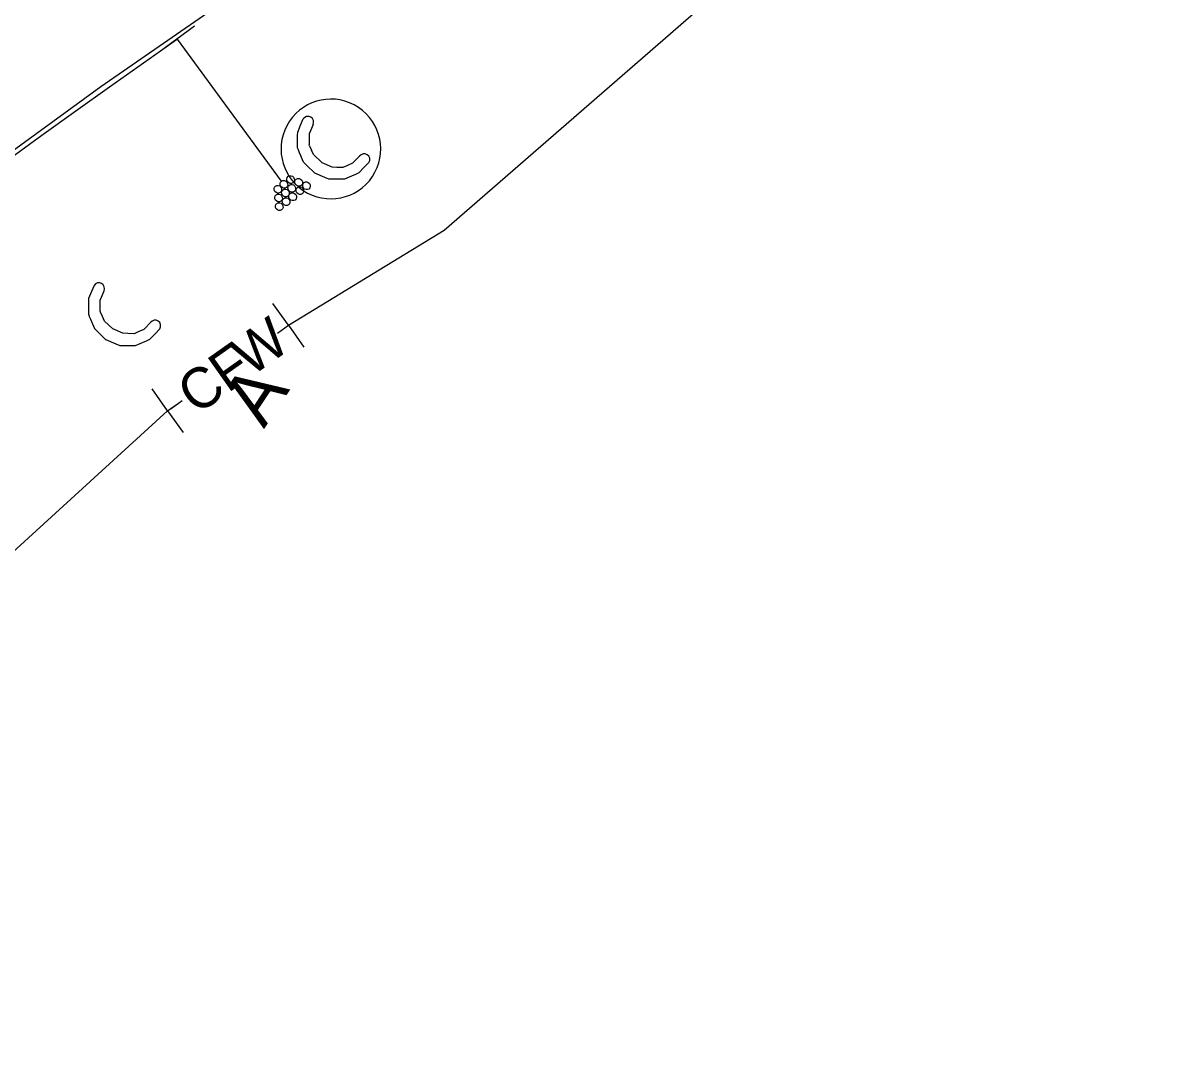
# Model space of a CAD drawing. Extents: x 2357856 to 2382083, y 331121 to 347536.
# Drawn here: x 2380922.9 to 2381137.7, y 332679.3 to 332872.8 of the extents above; entities that cross this region are included whole.
import ezdxf

# ---------------------------------------------------------------- set-up
doc = ezdxf.new("R2010")
doc.units = 0
for name, color, linetype in [('Coir Fiber Wattle Both CELL', 7, 'Continuous'), ('Matting and PSRM Summary Sheet CELL', 7, 'Continuous'), ('Old_Level_12', 7, 'Continuous'), ('P_NCDOT_Horizontal_Alignment_Station_Label', 7, 'Continuous'), ('P_NCDOT_Horizontal_Alignment_Tick_Small', 7, 'Continuous'), ('Sheet Data Field CELL', 7, 'Continuous'), ('Sheet_Named_Boundary', 7, 'Continuous')]:
    doc.layers.add(name, color=color, linetype=linetype)

msp = doc.modelspace()

# ---------------------------------------------------------------- linework, layer by layer
at = {"layer": 'Coir Fiber Wattle Both CELL'}
for radius, start, end in [(2079.999999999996, 122.68319408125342, 138.66862886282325), (2049.9999999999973, 124.90194270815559, 138.73574145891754)]:
    msp.add_arc((2382124.6181357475, 331188.5416706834), radius, start, end, dxfattribs=at)
at = {"layer": 'Matting and PSRM Summary Sheet CELL'}
for p, q in [((2380972.3583073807, 332816.4910176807), (2380969.47078194, 332820.5727081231)), ((2380970.316566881, 332815.0466216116), (2380972.3583073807, 332816.4910176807)), ((2380972.3583073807, 332816.4910176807), (2380975.245832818, 332812.4093272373)), ((2380949.840116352, 332800.5608901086), (2380946.952590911, 332804.6425805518)), ((2380949.840116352, 332800.5608901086), (2380951.881856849, 332802.0052861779)), ((2380950.49325491, 332800.99864639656), (2380952.535077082, 332802.44310024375)), ((2380949.840116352, 332800.5608901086), (2380952.727641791, 332796.47919966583))]:
    msp.add_line(p, q, dxfattribs=at)
at = {"layer": 'Old_Level_12'}
for p, q in [((2380948.234484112, 332867.4813884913), (2380954.8214911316, 332872.29770851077)), ((2380971.0851846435, 332843.3724340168), (2380951.6620882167, 332869.8132461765))]:
    msp.add_line(p, q, dxfattribs=at)
for centre in [(2380972.7568374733, 332843.6688509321), (2380970.387381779, 332841.8505370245), (2380971.52811148, 332842.76817887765), (2380971.7929625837, 332841.16992930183), (2380972.972539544, 332842.03457447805), (2380974.2710181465, 332843.1493205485), (2380974.497022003, 332841.6040676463), (2380975.7257479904, 332842.5047396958), (2380970.515087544, 332840.2332303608), (2380971.9206683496, 332839.5526226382), (2380973.1493943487, 332840.45329468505), (2380970.6427933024, 332838.6159236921)]:
    msp.add_ellipse(centre, major_axis=(-0.44292683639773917, 0.6042551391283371), ratio=0.9273984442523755, dxfattribs=at)
at = {"layer": 'P_NCDOT_Horizontal_Alignment_Station_Label'}
for p, q in [((2380976.4708975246, 332852.7741843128), (2380976.220539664, 332852.1927864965)), ((2380976.96671473, 332853.9132584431), (2380976.4708975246, 332852.7741843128)), ((2380976.217543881, 332851.3103058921), (2380976.2147963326, 332850.14921461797)), ((2380976.220539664, 332852.1927864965), (2380976.217543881, 332851.3103058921)), ((2380976.29185068, 332849.9778304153), (2380976.2147963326, 332850.14921461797)), ((2380976.29185068, 332849.9778304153), (2380976.65943075, 332849.1681692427)), ((2380977.054796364, 332848.3018021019), (2380976.65943075, 332849.1681692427)), ((2380977.054796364, 332848.3018021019), (2380978.576475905, 332846.84706928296)), ((2380978.584044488, 332846.8420332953), (2380978.576475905, 332846.84706928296)), ((2380978.584044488, 332846.8420332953), (2380980.4417666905, 332846.0154198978)), ((2380982.559772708, 332845.94923011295), (2380983.3133683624, 332846.2776790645)), ((2380983.3133683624, 332846.2776790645), (2380984.3983941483, 332846.75140182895)), ((2380984.584806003, 332846.9413006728), (2380984.3983941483, 332846.75140182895)), ((2380984.584806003, 332846.9413006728), (2380985.6267098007, 332848.0046782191)), ((2380980.4417666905, 332846.0154198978), (2380981.403695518, 332845.9841295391)), ((2380981.403695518, 332845.9841295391), (2380982.559772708, 332845.94923011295)), ((2380937.305813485, 332818.95781458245), (2380937.2287591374, 332819.12919878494)), ((2380938.0687591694, 332817.2817862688), (2380937.673393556, 332818.1481534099)), ((2380939.5980072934, 332815.8220174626), (2380939.5904387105, 332815.8270534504)), ((2380945.598768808, 332815.9212848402), (2380945.412356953, 332815.73138599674))]:
    msp.add_line(p, q, dxfattribs=at)
for points in [[(2380987.355627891, 332846.8542898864), (2380986.4968841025, 332845.95021660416), (2380985.4955799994, 332844.8966543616), (2380984.8843897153, 332844.6263236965), (2380984.1433986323, 332844.3004073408), (2380982.8302826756, 332843.72184468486), (2380982.7975049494, 332843.72181548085), (2380982.4445112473, 332843.72465268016), (2380982.383999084, 332843.72396842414), (2380981.618758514, 332843.7308507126), (2380981.086746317, 332843.73541943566), (2380979.9143021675, 332843.7457209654), (2380979.1462588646, 332844.0684017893), (2380977.267133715, 332844.8628487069), (2380977.2595651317, 332844.86788469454), (2380975.752993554, 332846.345323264), (2380975.1650014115, 332846.9221920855), (2380974.813788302, 332847.7564511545), (2380974.7392519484, 332847.93161964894), (2380974.441099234, 332848.6404880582), (2380974.214957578, 332849.1785981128), (2380974.163156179, 332849.3058809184), (2380974.048193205, 332849.5761949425), (2380974.0469269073, 332849.5824972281), (2380974.0647605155, 332850.7908775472), (2380974.080192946, 332851.86436267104), (2380974.090961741, 332852.5123632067), (2380974.6318996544, 332853.8094573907), (2380975.1086798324, 332854.95269111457)], [(2380936.1226426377, 332823.93267528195), (2380935.64586246, 332822.7894415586), (2380935.1049245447, 332821.4923473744), (2380935.0941557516, 332820.84434683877), (2380935.0787233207, 332819.77086171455), (2380935.0608897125, 332818.5624813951), (2380935.0621560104, 332818.5561791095), (2380935.1771189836, 332818.2858650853), (2380935.228920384, 332818.15858227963), (2380935.455062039, 332817.6204722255), (2380935.753214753, 332816.9116038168), (2380935.8277511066, 332816.73643532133), (2380936.1789642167, 332815.9021762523), (2380936.76695636, 332815.3253074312), (2380938.2735279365, 332813.84786886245), (2380938.28109652, 332813.8428328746), (2380940.1602216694, 332813.0483859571), (2380940.9282649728, 332812.7257051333), (2380942.1007091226, 332812.7154036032), (2380942.63272132, 332812.7108348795), (2380943.3979618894, 332812.70395259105), (2380943.458474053, 332812.7046368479), (2380943.8114677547, 332812.7017996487), (2380943.8442454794, 332812.70182885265), (2380945.157361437, 332813.2803915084), (2380945.8983525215, 332813.60630786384), (2380946.509542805, 332813.87663852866), (2380947.5108469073, 332814.9302007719), (2380948.369590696, 332815.8342740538)], [(2380946.6406726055, 332816.9846623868), (2380945.5987688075, 332815.9212848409), (2380945.412356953, 332815.73138599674), (2380944.327331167, 332815.2576632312), (2380943.5737355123, 332814.9292142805), (2380942.4176583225, 332814.9641137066), (2380941.455729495, 332814.99540406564), (2380939.5980072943, 332815.82201746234), (2380939.5904387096, 332815.82705345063), (2380938.06875917, 332817.28178626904), (2380937.6733935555, 332818.1481534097), (2380937.3058134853, 332818.9578145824), (2380937.2287591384, 332819.1291987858), (2380937.231506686, 332820.2902900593), (2380937.2345024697, 332821.17277066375), (2380937.4848603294, 332821.7541684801), (2380937.980677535, 332822.8932426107), (2380937.9813330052, 332822.89408683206)]]:
    msp.add_lwpolyline(points, dxfattribs=at)
for centre, radius, start, end in [((2380980.2778143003, 332849.3673332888), 9.294737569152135, 56.360981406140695, 146.3609814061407), ((2380980.2778143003, 332849.3673332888), 9.294737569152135, 326.3609814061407, 56.360981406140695), ((2380975.9976692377, 332854.36117492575), 1.0677984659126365, 335.2483434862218, 146.3609814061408), ((2380980.2778143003, 332849.3673332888), 9.294737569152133, 146.36098140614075, 236.36098140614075), ((2380986.491168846, 332847.4294840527), 1.0383341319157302, 326.36098140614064, 146.36098140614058), ((2380980.2778143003, 332849.3673332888), 9.294737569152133, 236.36098140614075, 326.3609814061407), ((2380937.011632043, 332823.3411590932), 1.0677984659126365, 335.2483434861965, 146.36098140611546), ((2380947.5051316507, 332816.40946822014), 1.0383341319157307, 326.3609814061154, 146.36098140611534)]:
    msp.add_arc(centre, radius, start, end, dxfattribs=at)
at = {"layer": 'Sheet Data Field CELL'}
msp.add_lwpolyline([(2380531.758397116, 332468.6549871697), (2380564.9991510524, 332507.18869358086), (2380582.8949095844, 332541.2021949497), (2380648.5233887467, 332612.53089040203), (2380680.759799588, 332645.20707670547), (2380717.6694683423, 332680.8876249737), (2380747.683205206, 332708.6242990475), (2380808.047430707, 332761.1962985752), (2380852.1199312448, 332797.0656274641), (2380899.232170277, 332833.23928289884), (2380937.3812848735, 332860.9858879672), (2380975.697266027, 332887.53603062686), (2381012.849422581, 332912.07621586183), (2381058.6131801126, 332940.75011563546), (2381095.3690434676, 332962.58995245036), (2381137.678231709, 332988.8089441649)], dxfattribs=at)
at = {"layer": 'Sheet_Named_Boundary'}
msp.add_line((2380822.549227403, 332684.4567180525), (2380949.840116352, 332800.5608901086), dxfattribs=at)
msp.add_lwpolyline([(2380972.3583073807, 332816.4910176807), (2381001.3889218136, 332834.24754505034), (2381068.3093186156, 332892.3878902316), (2381117.0595932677, 332934.7420592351)], dxfattribs=at)

# ---------------------------------------------------------------- texts
at = {"layer": 'Matting and PSRM Summary Sheet CELL'}
for s, p in [('W', (2380965.3142912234, 332806.75897679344)), ('F', (2380961.031341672, 332803.7465805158)), ('C', (2380955.2000715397, 332799.621343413))]:
    msp.add_text(s, height=7.535667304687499, rotation=35.2768757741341, dxfattribs=at).set_placement(p)
at = {"layer": 'P_NCDOT_Horizontal_Alignment_Tick_Small'}
msp.add_text('A', height=10, rotation=56.360981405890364, dxfattribs=at).set_placement((2380967.7888673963, 332797.1127607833))

doc.saveas('drawing.dxf')
